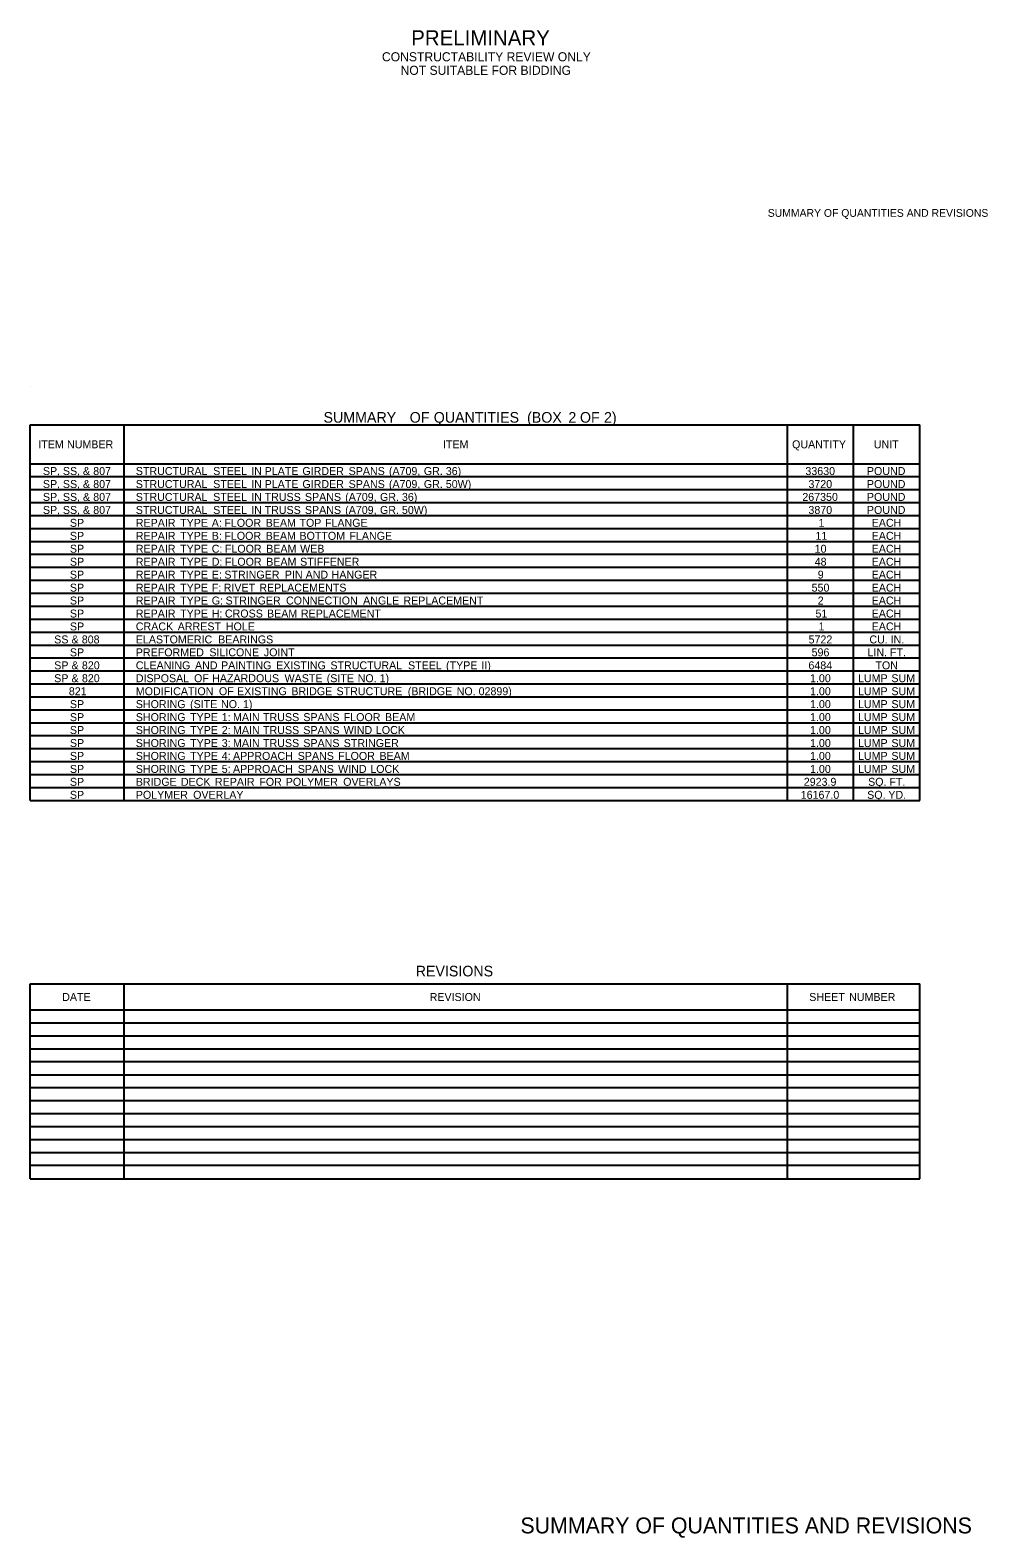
# Model space of a CAD drawing. Extents: x 107 to 7866, y 32 to 1473.
# Drawn here: x 7146 to 7866, y 40 to 1175 of the extents above; entities that cross this region are included whole.
import ezdxf

# ---------------------------------------------------------------- set-up
doc = ezdxf.new("R2010")
doc.units = 0
for name, color, linetype in [('Default', 7, 'Continuous'), ('R_Annotation', 7, 'Continuous'), ('R_Border', 7, 'Continuous'), ('R_Draft', 7, 'Continuous')]:
    doc.layers.add(name, color=color, linetype=linetype)

msp = doc.modelspace()

# ---------------------------------------------------------------- linework, layer by layer
at = {"layer": 'Default'}
for p, q in [((7145.8, 907.2), (7145.8, 907.2)), ((7145.8, 878), (7815.1, 878)), ((7145.8, 848.7), (7145.8, 878)), ((7216.5, 848.7), (7216.5, 878)), ((7715.7, 848.7), (7715.7, 878)), ((7715.7, 848.7), (7715.7, 878)), ((7765.4, 848.7), (7765.4, 878)), ((7815.1, 848.7), (7815.1, 878)), ((7145.8, 848.7), (7815.1, 848.7)), ((7145.8, 848.7), (7815.1, 848.7)), ((7145.8, 595.2), (7145.8, 848.7)), ((7145.8, 595.2), (7145.8, 848.7)), ((7216.5, 595.2), (7216.5, 848.7)), ((7216.5, 683), (7216.5, 848.7)), ((7715.7, 595.2), (7715.7, 848.7)), ((7715.7, 595.2), (7715.7, 848.7)), ((7765.4, 595.2), (7765.4, 848.7)), ((7765.4, 595.2), (7765.4, 848.7)), ((7815.1, 595.2), (7815.1, 848.7)), ((7145.8, 839), (7815.1, 839)), ((7145.8, 829.2), (7815.1, 829.2)), ((7145.8, 819.5), (7815.1, 819.5)), ((7145.8, 809.7), (7815.1, 809.7)), ((7145.8, 800), (7815.1, 800)), ((7145.8, 790.2), (7815.1, 790.2)), ((7145.8, 780.5), (7815.1, 780.5)), ((7145.8, 770.7), (7815.1, 770.7)), ((7145.8, 761), (7815.1, 761)), ((7145.8, 751.2), (7815.1, 751.2)), ((7145.8, 741.5), (7815.1, 741.5)), ((7145.8, 731.7), (7815.1, 731.7)), ((7145.8, 722), (7815.1, 722)), ((7145.8, 712.2), (7815.1, 712.2)), ((7145.8, 702.5), (7815.1, 702.5)), ((7145.8, 692.7), (7815.1, 692.7)), ((7145.8, 683), (7815.1, 683)), ((7216.5, 673.2), (7216.5, 683)), ((7145.8, 673.2), (7815.1, 673.2)), ((7216.5, 673.2), (7627.9, 673.2)), ((7216.5, 595.2), (7216.5, 673.2)), ((7627.9, 673.2), (7815.1, 673.2)), ((7145.8, 663.5), (7815.1, 663.5)), ((7145.8, 653.7), (7815.1, 653.7)), ((7145.8, 644), (7815.1, 644)), ((7145.8, 634.2), (7815.1, 634.2)), ((7145.8, 624.5), (7815.1, 624.5)), ((7145.8, 614.7), (7815.1, 614.7)), ((7145.8, 605), (7815.1, 605)), ((7145.8, 595.2), (7815.1, 595.2)), ((7145.8, 457), (7815.1, 457)), ((7145.8, 457), (7216.5, 457)), ((7145.8, 310.3), (7145.8, 457)), ((7145.8, 310.3), (7145.8, 457)), ((7216.5, 310.3), (7216.5, 457)), ((7715.7, 457), (7815.1, 457)), ((7715.7, 437.5), (7715.7, 457)), ((7715.7, 310.3), (7715.7, 457)), ((7815.1, 310.3), (7815.1, 457)), ((7815.1, 310.3), (7815.1, 457)), ((7145.8, 437.5), (7815.1, 437.5)), ((7145.8, 427.7), (7815.1, 427.7)), ((7145.8, 418), (7815.1, 418)), ((7145.8, 408.2), (7815.1, 408.2)), ((7145.8, 398.5), (7815.1, 398.5)), ((7145.8, 388.7), (7815.1, 388.7)), ((7145.8, 379), (7815.1, 379)), ((7145.8, 369.2), (7815.1, 369.2)), ((7145.8, 359.5), (7815.1, 359.5)), ((7145.8, 349.7), (7815.1, 349.7)), ((7145.8, 340), (7815.1, 340)), ((7145.8, 330.2), (7815.1, 330.2)), ((7145.8, 320.5), (7815.1, 320.5)), ((7145.8, 310.3), (7815.1, 310.3))]:
    msp.add_line(p, q, dxfattribs=at)

# ---------------------------------------------------------------- texts
for s, height, p in [('                               SUMMARY', 8, (7274.4, 879.6)), (' OF', 8, (7428.4, 879.6)), (' QUANTITIES', 8, (7446.5, 879.6)), (' (BOX', 8, (7516.7, 879.6)), (' 2', 8, (7547.8, 879.6)), (' OF', 8, (7556.5, 879.6)), (' 2)', 8, (7574.6, 879.6)), ('ITEM', 6, (7151.9, 860.3)), (' NUMBER', 6, (7171.3, 860.3)), ('ITEM', 6, (7456.4, 860.3)), ('QUANTITY', 6, (7719.1, 860.3)), ('UNIT', 6, (7780.6, 860.3)), ('SP,', 6, (7155.4, 840.2)), (' SS,', 6, (7168.2, 840.2)), (' &', 6, (7183.3, 840.2)), (' 807', 6, (7191, 840.2)), ('STRUCTURAL', 6, (7225.3, 840.2)), (' STEEL', 6, (7281.3, 840.2)), (' IN', 6, (7309.9, 840.2)), (' PLATE', 6, (7320, 840.2)), (' GIRDER', 6, (7348.4, 840.2)), (' SPANS', 6, (7383.2, 840.2)), (' (A709,', 6, (7413.5, 840.2)), (' GR.', 6, (7439.8, 840.2)), (' 36)', 6, (7456.3, 840.2)), ('33630', 6, (7729.1, 840.2)), ('POUND', 6, (7775.4, 840.2)), ('SP,', 6, (7155.4, 830.4)), (' SS,', 6, (7168.2, 830.4)), (' &', 6, (7183.3, 830.4)), (' 807', 6, (7191, 830.4)), ('STRUCTURAL', 6, (7225.3, 830.4)), (' STEEL', 6, (7281.3, 830.4)), (' IN', 6, (7309.9, 830.4)), (' PLATE', 6, (7320, 830.4)), (' GIRDER', 6, (7348.4, 830.4)), (' SPANS', 6, (7383.2, 830.4)), (' (A709,', 6, (7413.5, 830.4)), (' GR.', 6, (7439.8, 830.4)), (' 50W)', 6, (7456.3, 830.4)), ('3720', 6, (7731.4, 830.4)), ('POUND', 6, (7775.4, 830.4)), ('SP,', 6, (7155.4, 820.7)), (' SS,', 6, (7168.2, 820.7)), (' &', 6, (7183.3, 820.7)), (' 807', 6, (7191, 820.7)), ('STRUCTURAL', 6, (7225.3, 820.7)), (' STEEL', 6, (7281.3, 820.7)), (' IN', 6, (7309.9, 820.7)), (' TRUSS', 6, (7320, 820.7)), (' SPANS', 6, (7350.3, 820.7)), (' (A709,', 6, (7380.6, 820.7)), (' GR.', 6, (7406.8, 820.7)), (' 36)', 6, (7423.3, 820.7)), ('267350', 6, (7726.8, 820.7)), ('POUND', 6, (7775.4, 820.7)), ('SP,', 6, (7155.4, 810.9)), (' SS,', 6, (7168.2, 810.9)), ('SP', 6, (7175.7, 801.2)), (' &', 6, (7183.3, 810.9)), (' 807', 6, (7191, 810.9)), ('STRUCTURAL', 6, (7225.3, 810.9)), ('REPAIR', 6, (7225.3, 801.2)), (' TYPE', 6, (7256.4, 801.2)), (' A:', 6, (7280.2, 801.2)), (' STEEL', 6, (7281.3, 810.9)), (' FLOOR', 6, (7289.7, 801.2)), (' IN', 6, (7309.9, 810.9)), (' TRUSS', 6, (7320, 810.9)), (' BEAM', 6, (7320.8, 801.2)), (' TOP', 6, (7346.2, 801.2)), (' SPANS', 6, (7350.3, 810.9)), (' FLANGE', 6, (7365.4, 801.2)), (' (A709,', 6, (7380.6, 810.9)), (' GR.', 6, (7406.8, 810.9)), (' 50W)', 6, (7423.3, 810.9)), ('3870', 6, (7731.4, 810.9)), ('1', 6, (7739, 801.2)), ('POUND', 6, (7775.4, 810.9)), ('EACH', 6, (7779, 801.2)), ('SP', 6, (7175.7, 791.4)), ('REPAIR', 6, (7225.3, 791.4)), (' TYPE', 6, (7256.4, 791.4)), (' B:', 6, (7280.2, 791.4)), (' FLOOR', 6, (7289.7, 791.4)), (' BEAM', 6, (7320.8, 791.4)), (' BOTTOM', 6, (7346.2, 791.4)), (' FLANGE', 6, (7383.8, 791.4)), ('11', 6, (7736.7, 791.4)), ('EACH', 6, (7779, 791.4)), ('SP', 6, (7175.7, 781.7)), ('REPAIR', 6, (7225.3, 781.7)), (' TYPE', 6, (7256.4, 781.7)), (' C:', 6, (7280.2, 781.7)), (' FLOOR', 6, (7290.1, 781.7)), (' BEAM', 6, (7321.2, 781.7)), (' WEB', 6, (7346.7, 781.7)), ('10', 6, (7736.1, 781.7)), ('EACH', 6, (7779, 781.7)), ('SP', 6, (7175.7, 771.9)), ('REPAIR', 6, (7225.3, 771.9)), (' TYPE', 6, (7256.4, 771.9)), (' D:', 6, (7280.2, 771.9)), (' FLOOR', 6, (7290.1, 771.9)), (' BEAM', 6, (7321.2, 771.9)), (' STIFFENER', 6, (7346.7, 771.9)), ('48', 6, (7736.1, 771.9)), ('EACH', 6, (7779, 771.9)), ('SP', 6, (7175.7, 762.2)), ('REPAIR', 6, (7225.3, 762.2)), (' TYPE', 6, (7256.4, 762.2)), (' E:', 6, (7280.2, 762.2)), (' STRINGER', 6, (7289.7, 762.2)), (' PIN', 6, (7335.2, 762.2)), (' AND', 6, (7350.8, 762.2)), (' HANGER', 6, (7370.4, 762.2)), ('9', 6, (7738.4, 762.2)), ('EACH', 6, (7779, 762.2)), ('SP', 6, (7175.7, 752.4)), ('REPAIR', 6, (7225.3, 752.4)), (' TYPE', 6, (7256.4, 752.4)), (' F:', 6, (7280.2, 752.4)), (' RIVET', 6, (7289.2, 752.4)), (' REPLACEMENTS', 6, (7316, 752.4)), ('550', 6, (7733.8, 752.4)), ('EACH', 6, (7779, 752.4)), ('SP', 6, (7175.7, 742.7)), ('SP', 6, (7175.7, 732.9)), ('REPAIR', 6, (7225.3, 742.7)), ('REPAIR', 6, (7225.3, 732.9)), (' TYPE', 6, (7256.4, 742.7)), (' TYPE', 6, (7256.4, 732.9)), (' G:', 6, (7280.2, 742.7)), (' H:', 6, (7280.2, 732.9)), (' CROSS', 6, (7290.1, 732.9)), (' STRINGER', 6, (7290.6, 742.7)), (' BEAM', 6, (7321.8, 732.9)), (' CONNECTION', 6, (7336.1, 742.7)), (' REPLACEMENT', 6, (7347.3, 732.9)), (' ANGLE', 6, (7394.1, 742.7)), (' REPLACEMENT', 6, (7424.4, 742.7)), ('51', 6, (7736.7, 732.9)), ('2', 6, (7738.4, 742.7)), ('EACH', 6, (7779, 742.7)), ('EACH', 6, (7779, 732.9)), ('SP', 6, (7175.7, 723.2)), ('CRACK', 6, (7225.3, 723.2)), (' ARREST', 6, (7254.6, 723.2)), (' HOLE', 6, (7290.8, 723.2)), ('1', 6, (7739, 723.2)), ('EACH', 6, (7779, 723.2)), ('SS', 6, (7163.9, 713.4)), (' &', 6, (7174.7, 713.4)), (' 808', 6, (7182.4, 713.4)), ('ELASTOMERIC', 6, (7225.3, 713.4)), (' BEARINGS', 6, (7285, 713.4)), ('5722', 6, (7731.5, 713.4)), ('CU.', 6, (7777.3, 713.4)), (' IN.', 6, (7791, 713.4)), ('SP', 6, (7175.7, 703.7)), ('PREFORMED', 6, (7225.3, 703.7)), (' SILICONE', 6, (7278.4, 703.7)), (' JOINT', 6, (7319.4, 703.7)), ('596', 6, (7733.8, 703.7)), ('LIN.', 6, (7775.9, 703.7)), (' FT.', 6, (7790.5, 703.7)), ('SP', 6, (7163.9, 693.9)), (' &', 6, (7174.7, 693.9)), (' 820', 6, (7182.5, 693.9)), ('CLEANING', 6, (7225.3, 693.9)), (' AND', 6, (7267.6, 693.9)), (' PAINTING', 6, (7287.2, 693.9)), (' EXISTING', 6, (7328.6, 693.9)), (' STRUCTURAL', 6, (7369.5, 693.9)), (' STEEL', 6, (7427.9, 693.9)), (' (TYPE', 6, (7456.5, 693.9)), (' II)', 6, (7483.1, 693.9)), ('6484', 6, (7731.4, 693.9)), ('TON', 6, (7781.8, 693.9)), ('SP', 6, (7163.9, 684.2)), (' &', 6, (7174.7, 684.2)), (' 820', 6, (7182.5, 684.2)), ('DISPOSAL', 6, (7225.3, 684.2)), (' OF', 6, (7266.9, 684.2)), (' HAZARDOUS', 6, (7280.5, 684.2)), (' WASTE', 6, (7335, 684.2)), (' (SITE', 6, (7366.7, 684.2)), (' NO.', 6, (7390, 684.2)), (' 1)', 6, (7406.5, 684.2)), ('1.00', 6, (7732.6, 684.2)), ('LUMP', 6, (7768.7, 684.2)), (' SUM', 6, (7791.6, 684.2)), ('821', 6, (7174.9, 674.4)), ('SP', 6, (7175.7, 664.7)), ('SHORING', 6, (7225.3, 664.7)), ('MODIFICATION', 6, (7225.3, 674.4)), (' (SITE', 6, (7263.9, 664.7)), (' OF', 6, (7285.6, 674.4)), (' NO.', 6, (7287.2, 664.7)), (' EXISTING', 6, (7299.2, 674.4)), (' 1)', 6, (7303.7, 664.7)), (' BRIDGE', 6, (7340.1, 674.4)), (' STRUCTURE', 6, (7374.1, 674.4)), (' (BRIDGE', 6, (7427.7, 674.4)), (' NO.', 6, (7464.5, 674.4)), (' 02899)', 6, (7481, 674.4)), ('1.00', 6, (7732.6, 674.4)), ('1.00', 6, (7732.6, 664.7)), ('LUMP', 6, (7768.7, 674.4)), ('LUMP', 6, (7768.7, 664.7)), (' SUM', 6, (7791.6, 674.4)), (' SUM', 6, (7791.6, 664.7)), ('SP', 6, (7175.7, 654.9)), ('SHORING', 6, (7225.3, 654.9)), (' TYPE', 6, (7263.9, 654.9)), (' 1:', 6, (7287.7, 654.9)), (' MAIN', 6, (7296.2, 654.9)), (' TRUSS', 6, (7318.8, 654.9)), (' SPANS', 6, (7349.1, 654.9)), (' FLOOR', 6, (7379.5, 654.9)), (' BEAM', 6, (7410.6, 654.9)), ('1.00', 6, (7732.6, 654.9)), ('LUMP', 6, (7768.7, 654.9)), (' SUM', 6, (7791.6, 654.9)), ('SP', 6, (7175.7, 645.2)), ('SHORING', 6, (7225.3, 645.2)), (' TYPE', 6, (7263.9, 645.2)), (' 2:', 6, (7287.7, 645.2)), (' MAIN', 6, (7296.2, 645.2)), (' TRUSS', 6, (7318.8, 645.2)), (' SPANS', 6, (7349.1, 645.2)), (' WIND', 6, (7379.5, 645.2)), (' LOCK', 6, (7403.7, 645.2)), ('1.00', 6, (7732.6, 645.2)), ('LUMP', 6, (7768.7, 645.2)), (' SUM', 6, (7791.6, 645.2)), ('SP', 6, (7175.7, 635.4)), ('SHORING', 6, (7225.3, 635.4)), (' TYPE', 6, (7263.9, 635.4)), (' 3:', 6, (7287.7, 635.4)), (' MAIN', 6, (7296.2, 635.4)), (' TRUSS', 6, (7318.8, 635.4)), (' SPANS', 6, (7349.1, 635.4)), (' STRINGER', 6, (7379.5, 635.4)), ('1.00', 6, (7732.6, 635.4)), ('LUMP', 6, (7768.7, 635.4)), (' SUM', 6, (7791.6, 635.4)), ('SP', 6, (7175.7, 625.7)), ('SHORING', 6, (7225.3, 625.7)), (' TYPE', 6, (7263.9, 625.7)), (' 4:', 6, (7287.7, 625.7)), (' APPROACH', 6, (7296.2, 625.7)), (' SPANS', 6, (7344.9, 625.7)), (' FLOOR', 6, (7375.3, 625.7)), (' BEAM', 6, (7406.4, 625.7)), ('1.00', 6, (7732.6, 625.7)), ('LUMP', 6, (7768.7, 625.7)), (' SUM', 6, (7791.6, 625.7)), ('SP', 6, (7175.7, 615.9)), ('SHORING', 6, (7225.3, 615.9)), (' TYPE', 6, (7263.9, 615.9)), (' 5:', 6, (7287.7, 615.9)), (' APPROACH', 6, (7296.2, 615.9)), (' SPANS', 6, (7344.9, 615.9)), (' WIND', 6, (7375.3, 615.9)), (' LOCK', 6, (7399.5, 615.9)), ('1.00', 6, (7732.6, 615.9)), ('LUMP', 6, (7768.7, 615.9)), (' SUM', 6, (7791.6, 615.9)), ('SP', 6, (7175.7, 606.2)), ('SP', 6, (7175.7, 596.4)), ('BRIDGE', 6, (7225.3, 606.2)), ('POLYMER', 6, (7225.3, 596.4)), (' DECK', 6, (7257, 606.2)), (' OVERLAY', 6, (7266.2, 596.4)), (' REPAIR', 6, (7282.6, 606.2)), (' FOR', 6, (7316, 606.2)), (' POLYMER', 6, (7335.9, 606.2)), (' OVERLAYS', 6, (7379.1, 606.2)), ('16167.0', 6, (7725.6, 596.4)), ('2923.9', 6, (7727.9, 606.2)), ('SQ.', 6, (7775.6, 596.4)), ('SQ.', 6, (7776.3, 606.2)), (' YD.', 6, (7789.3, 596.4)), (' FT.', 6, (7790.1, 606.2)), ('REVISIONS', 8, (7435.9, 462.7)), ('DATE', 6, (7169.9, 444.2)), ('REVISION', 6, (7446.4, 444.2)), ('SHEET', 6, (7732, 444.2)), (' NUMBER', 6, (7759.8, 444.2))]:
    msp.add_text(s, height=height, dxfattribs=at).set_placement(p)
at = {"layer": 'R_Annotation'}
msp.add_text('SUMMARY OF QUANTITIES AND REVISIONS', height=12, rotation=360, dxfattribs=at).set_placement((7514.7, 43.3))
at = {"layer": 'R_Border'}
msp.add_text('SUMMARY OF QUANTITIES AND REVISIONS', height=5.862, dxfattribs=at).set_placement((7700.8, 1034.6))
at = {"layer": 'R_Draft'}
for s, height, p in [('PRELIMINARY', 11.508, (7432.5, 1163.6)), ('CONSTRUCTABILITY REVIEW ONLY', 6.823, (7410.5, 1151.7)), ('NOT SUITABLE FOR BIDDING', 6.823, (7424.5, 1141.5))]:
    msp.add_text(s, height=height, rotation=0, dxfattribs=at).set_placement(p)

doc.saveas('drawing.dxf')
